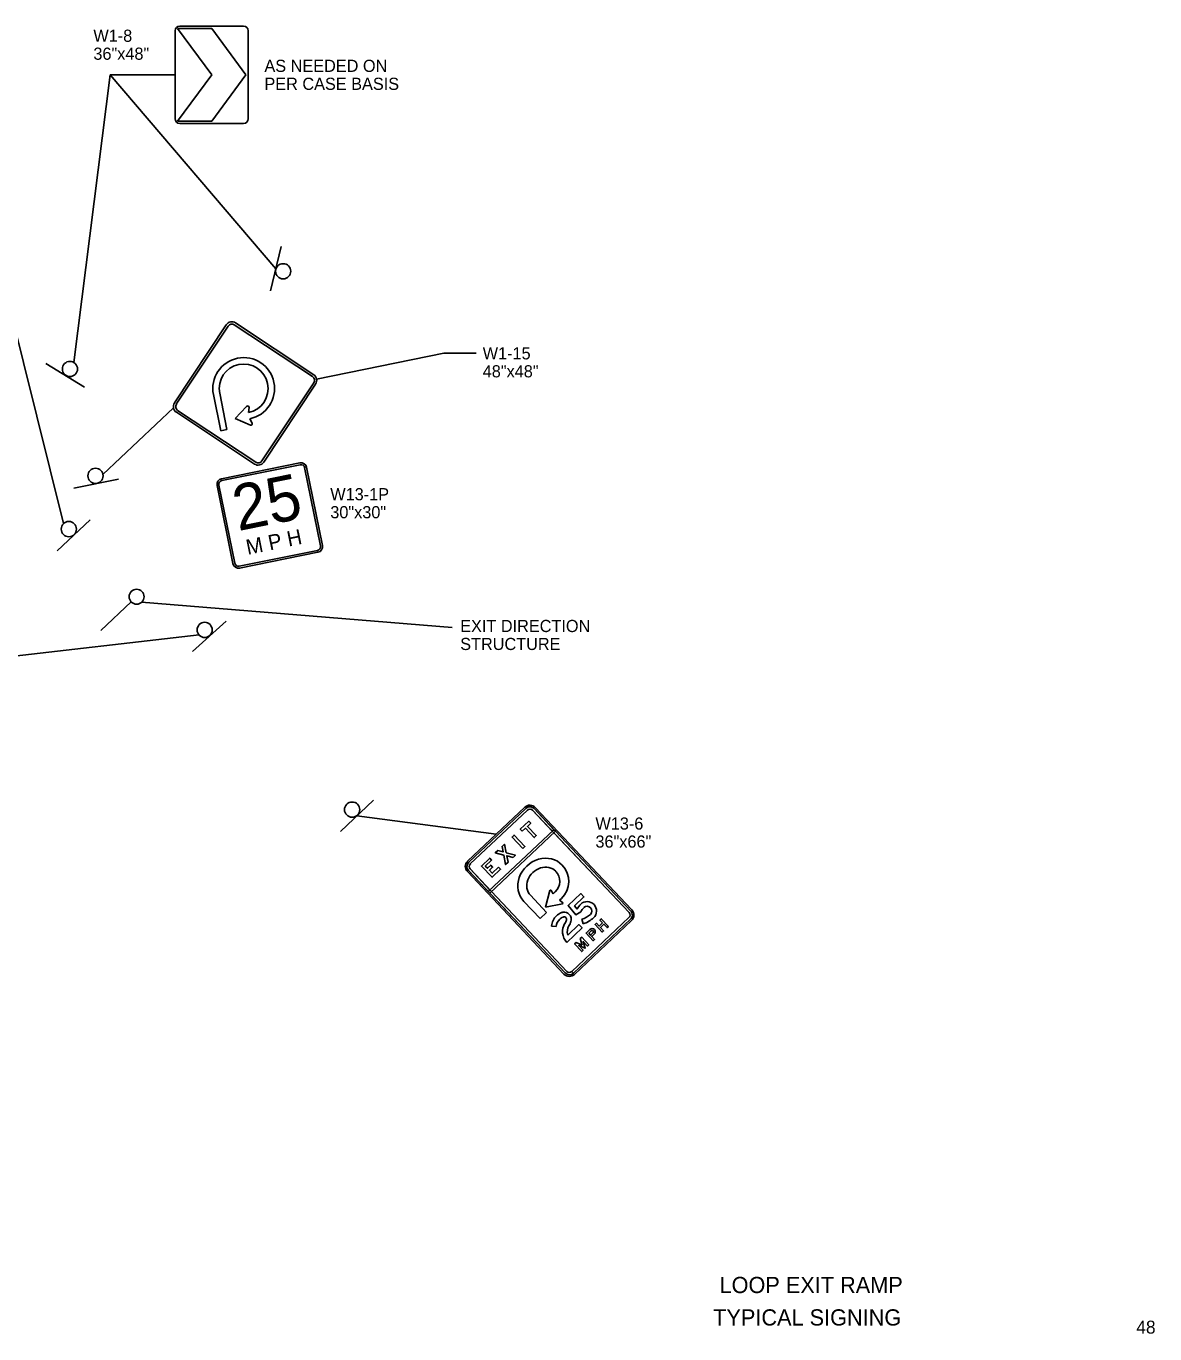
# Model space of a CAD drawing. Extents: x 571683 to 574814, y 1530838 to 1532905.
# Drawn here: x 573075 to 574814, y 1530889 to 1532905 of the extents above; entities that cross this region are included whole.
import ezdxf

# ---------------------------------------------------------------- set-up
doc = ezdxf.new("R2010")
doc.units = 0
for name, color, linetype in [('SignDetail', 7, 'Continuous'), ('SignPanel', 7, 'Continuous'), ('TextLabel', 7, 'Continuous'), ('TextMisc', 7, 'Continuous'), ('TextShtNo', 7, 'Continuous')]:
    doc.layers.add(name, color=color, linetype=linetype)

msp = doc.modelspace()

# ---------------------------------------------------------------- linework, layer by layer
at = {"layer": 'SignDetail'}
for p, q in [((573148.6, 1532386.1), (573204.7, 1532829.3)), ((573204.7, 1532829.3), (573304.7, 1532829.5)), ((573459.6, 1532530.7), (573204.7, 1532829.3)), ((573132.8, 1532137.8), (572992.3, 1532700.8)), ((573467.8, 1532564.8), (573451.5, 1532496.7)), ((573522.6, 1532360.6), (573718.6, 1532400.3)), ((573718.6, 1532400.3), (573768.6, 1532400.3)), ((573105.3, 1532384.6), (573165.1, 1532348.3)), ((573193.3, 1532213.7), (573302, 1532316)), ((573148.7, 1532192.4), (573217.3, 1532206.3)), ((573122.7, 1532095.6), (573173.7, 1532143.6)), ((573236.8, 1532017.1), (573190.1, 1531973.2)), ((573253, 1532016.6), (573731.4, 1531977.7)), ((573331.2, 1531940.7), (573383.2, 1531987.6)), ((572955.7, 1531921.8), (573341.4, 1531966.1)), ((573559.2, 1531663.3), (573610.1, 1531711.3)), ((573584.7, 1531687.3), (573799.4, 1531659.1))]:
    msp.add_line(p, q, dxfattribs=at)
for centre, radius in [((573471.1, 1532526.7), 11.7), ((573142.5, 1532376.1), 11.7), ((573181.9, 1532211.4), 11.7), ((573140.8, 1532129.3), 11.7), ((573140.8, 1532129.3), 11.7), ((573245.2, 1532025), 11.5), ((573245.2, 1532025), 11.5), ((573350.1, 1531973.9), 11.7), ((573577.3, 1531696.9), 11.7)]:
    msp.add_circle(centre, radius, dxfattribs=at)
at = {"layer": 'SignPanel'}
for p, q in [((573311.7, 1532904.5), (573410.1, 1532904.5)), ((573304.7, 1532897.5), (573304.7, 1532897.5)), ((573360.9, 1532829.5), (573308.2, 1532901)), ((573308.2, 1532901), (573360.9, 1532901)), ((573360.9, 1532901), (573413.7, 1532829.5)), ((573308.2, 1532758), (573360.9, 1532829.5)), ((573413.7, 1532829.5), (573360.9, 1532758)), ((573360.9, 1532758), (573308.2, 1532758)), ((573383.4, 1532444.2), (573303.6, 1532323.7)), ((573386.3, 1532442.3), (573306.4, 1532321.8)), ((573516.3, 1532364.3), (573395.8, 1532444.2)), ((573518.2, 1532367.2), (573397.7, 1532447.1)), ((573384.5, 1532282.8), (573373.3, 1532338.6)), ((573438.3, 1532234.4), (573518.2, 1532354.8)), ((573441.2, 1532232.5), (573521.1, 1532352.9)), ((573363.5, 1532336.6), (573374.8, 1532280.8)), ((573414.8, 1532318.5), (573397, 1532299.9)), ((573306.5, 1532309.4), (573426.9, 1532229.6)), ((573308.4, 1532312.3), (573428.8, 1532232.4)), ((573397, 1532299.9), (573420.6, 1532289.5)), ((573417.6, 1532309.1), (573418.5, 1532316.8)), ((573423.3, 1532292.6), (573419.6, 1532299.4)), ((573374.8, 1532280.8), (573384.5, 1532282.8)), ((573496.7, 1532231.4), (573376.1, 1532207)), ((573497.3, 1532228.6), (573376.7, 1532204.1)), ((573528.6, 1532103.4), (573504.2, 1532224)), ((573531.5, 1532103.9), (573507.1, 1532224.6)), ((573372.1, 1532197.2), (573396.5, 1532076.6)), ((573369.2, 1532196.7), (573393.6, 1532076.1)), ((573403.4, 1532072.1), (573524, 1532096.5)), ((573404, 1532069.2), (573524.6, 1532093.6)), ((573843.4, 1531700.6), (573755.4, 1531617.5)), ((573845.1, 1531698.7), (573757.1, 1531615.7)), ((573845.1, 1531698.7), (573757.1, 1531615.7)), ((573847.5, 1531696.2), (573759.5, 1531613.2)), ((573759.5, 1531613.2), (573847.5, 1531696.2)), ((573759.5, 1531613.2), (573847.5, 1531696.2)), ((574004.2, 1531538.1), (573855.3, 1531696)), ((573855.3, 1531696), (574004.2, 1531538.1)), ((573855.3, 1531696), (573885.8, 1531663.6)), ((574006.7, 1531540.5), (573857.8, 1531698.4)), ((573888.4, 1531666), (573857.8, 1531698.4)), ((574008.5, 1531542.2), (573859.6, 1531700.1)), ((573888.4, 1531666), (573787.2, 1531570.6)), ((573888.4, 1531666), (573787.2, 1531570.6)), ((573888.4, 1531666), (573787.2, 1531570.6)), ((573789.6, 1531568.1), (573890.8, 1531663.5)), ((573789.6, 1531568.1), (573890.8, 1531663.5)), ((573789.6, 1531568.1), (573890.8, 1531663.5)), ((573885.8, 1531663.6), (573888.4, 1531666)), ((573890.8, 1531663.5), (573888.2, 1531661.1)), ((573888.2, 1531661.1), (574004.2, 1531538.1)), ((573890.8, 1531663.5), (573888.4, 1531666)), ((573890.8, 1531663.5), (573888.4, 1531666)), ((573890.8, 1531663.5), (573888.4, 1531666)), ((574006.7, 1531540.5), (573890.8, 1531663.5)), ((573754.9, 1531601.3), (573903.8, 1531443.4)), ((573756.7, 1531603), (573905.6, 1531445.1)), ((573756.7, 1531603), (573787.2, 1531570.6)), ((573759.3, 1531605.4), (573908.2, 1531447.6)), ((573908.2, 1531447.6), (573759.3, 1531605.4)), ((573789.8, 1531573), (573759.3, 1531605.4)), ((573787.2, 1531570.6), (573789.8, 1531573)), ((573884.2, 1531572.4), (573887.2, 1531567.3)), ((573787.2, 1531570.6), (573789.6, 1531568.1)), ((573787.2, 1531570.6), (573789.6, 1531568.1)), ((573787.2, 1531570.6), (573789.6, 1531568.1)), ((573792.2, 1531570.5), (573789.6, 1531568.1)), ((573789.6, 1531568.1), (573905.6, 1531445.1)), ((573908.2, 1531447.6), (573792.2, 1531570.5)), ((573866.9, 1531529.1), (573842, 1531555.4)), ((573852.1, 1531564.8), (573876.9, 1531538.5)), ((573875.4, 1531546.6), (573882, 1531572.1)), ((573887.2, 1531567.3), (573890.4, 1531570.2)), ((573899.8, 1531560.1), (573896.7, 1531557.3)), ((573896.7, 1531557.3), (573901.7, 1531553.9)), ((573876.9, 1531538.5), (573866.9, 1531529.1)), ((573901.3, 1531551.8), (573875.4, 1531546.6)), ((573915.9, 1531447.3), (574003.9, 1531530.4)), ((574003.9, 1531530.4), (573916, 1531447.3)), ((574003.9, 1531530.4), (573916, 1531447.3)), ((573918.4, 1531444.8), (574006.4, 1531527.8)), ((573918.4, 1531444.8), (574006.4, 1531527.8)), ((573920.1, 1531443), (574008.1, 1531526)), ((573933.5, 1531521), (573931.4, 1531527.8)), ((573933.5, 1531521), (573931.4, 1531527.8)), ((573933.5, 1531521), (573931.4, 1531527.8)), ((573942, 1531506.5), (573945.8, 1531510)), ((573942, 1531506.5), (573945.8, 1531510)), ((573942, 1531506.5), (573945.8, 1531510)), ((573946.7, 1531501.5), (573950.5, 1531505)), ((573918.3, 1531444.8), (573915.9, 1531447.3)), ((573918.3, 1531444.8), (573915.9, 1531447.3)), ((573916, 1531447.3), (573918.4, 1531444.8)), ((573916, 1531447.3), (573918.4, 1531444.8))]:
    msp.add_line(p, q, dxfattribs=at)
for points in [[(573304.7, 1532761.6), (573304.7, 1532897.5)], [(573417.2, 1532897.5), (573417.2, 1532761.6)], [(573410.1, 1532754.5), (573311.7, 1532754.5)], [(573929.9, 1531539.4), (573922.2, 1531534.6), (573910.2, 1531549.1), (573929.7, 1531567.5), (573934.6, 1531562.3), (573920.1, 1531548.5), (573924, 1531543.7)], [(573929.9, 1531539.4), (573922.2, 1531534.6), (573910.2, 1531549.1), (573929.7, 1531567.5), (573934.6, 1531562.3), (573920.1, 1531548.5), (573924, 1531543.7)], [(573929.9, 1531539.4), (573922.2, 1531534.6), (573910.2, 1531549.1), (573929.7, 1531567.5), (573934.6, 1531562.3), (573920.1, 1531548.5), (573924, 1531543.7)], [(573891.7, 1531516.7), (573884.5, 1531517.5)], [(573891.7, 1531516.7), (573884.5, 1531517.5)], [(573891.7, 1531516.7), (573884.5, 1531517.5)], [(573909.7, 1531503.6), (573926.9, 1531519.8), (573931.8, 1531514.6), (573908.3, 1531492.3)], [(573909.7, 1531503.6), (573926.9, 1531519.8), (573931.8, 1531514.6), (573908.3, 1531492.3)], [(573909.7, 1531503.6), (573926.9, 1531519.8), (573931.8, 1531514.6), (573908.3, 1531492.3)], [(573943.8, 1531512.1), (573938, 1531506.6), (573948.9, 1531494.9), (573951, 1531496.9), (573946.7, 1531501.5)], [(573943.8, 1531512.1), (573938, 1531506.6), (573948.9, 1531494.9), (573951, 1531496.9), (573942, 1531506.5)], [(573943.8, 1531512.1), (573938, 1531506.6), (573948.9, 1531494.9), (573951, 1531496.9), (573942, 1531506.5)], [(573948.5, 1531507.1), (573944.8, 1531503.6), (573942, 1531506.5)], [(573948.5, 1531507.1), (573944.8, 1531503.6), (573946.7, 1531501.5), (573950.5, 1531505)], [(573948.5, 1531507.1), (573944.8, 1531503.6), (573946.7, 1531501.5), (573950.5, 1531505)]]:
    msp.add_lwpolyline(points, dxfattribs=at)
for points in [[(573839.5, 1531663.5), (573844.5, 1531668.2), (573858, 1531653.9), (573861.1, 1531656.8), (573847.6, 1531671.1), (573852.6, 1531675.8), (573849.6, 1531679), (573836.5, 1531666.6)], [(573839.5, 1531663.5), (573844.5, 1531668.2), (573858, 1531653.9), (573861.1, 1531656.8), (573847.6, 1531671.1), (573852.6, 1531675.8), (573849.6, 1531679), (573836.5, 1531666.6)], [(573839.5, 1531663.5), (573844.5, 1531668.2), (573858, 1531653.9), (573861.1, 1531656.8), (573847.6, 1531671.1), (573852.6, 1531675.8), (573849.6, 1531679), (573836.5, 1531666.6)], [(573840.3, 1531637.2), (573823.9, 1531654.7), (573827, 1531657.6), (573843.5, 1531640.2)], [(573840.3, 1531637.2), (573823.9, 1531654.7), (573827, 1531657.6), (573843.5, 1531640.2)], [(573840.3, 1531637.2), (573823.9, 1531654.7), (573827, 1531657.6), (573843.5, 1531640.2)], [(573825.4, 1531623.1), (573815.7, 1531625.7), (573817.7, 1531615.8), (573813.9, 1531612.3), (573811.1, 1531626.9), (573798, 1531630.3), (573801.7, 1531633.8), (573810.1, 1531631.6), (573808.4, 1531640.1), (573812.1, 1531643.6), (573814.8, 1531630.4), (573829.1, 1531626.6)], [(573825.4, 1531623.1), (573815.7, 1531625.7), (573817.7, 1531615.8), (573813.9, 1531612.3), (573811.1, 1531626.9), (573798, 1531630.3), (573801.7, 1531633.8), (573810.1, 1531631.6), (573808.4, 1531640.1), (573812.1, 1531643.6), (573814.8, 1531630.4), (573829.1, 1531626.6)], [(573825.4, 1531623.1), (573815.7, 1531625.7), (573817.7, 1531615.8), (573813.9, 1531612.3), (573811.1, 1531626.9), (573798, 1531630.3), (573801.7, 1531633.8), (573810.1, 1531631.6), (573808.4, 1531640.1), (573812.1, 1531643.6), (573814.8, 1531630.4), (573829.1, 1531626.6)], [(573803.1, 1531608.1), (573793.2, 1531598.7), (573788.8, 1531603.4), (573793.9, 1531608.2), (573790.9, 1531611.4), (573785.8, 1531606.5), (573782.6, 1531609.8), (573792.3, 1531619), (573789.4, 1531622.1), (573776.5, 1531610), (573793, 1531592.6), (573806.1, 1531604.9)], [(573803.1, 1531608.1), (573793.2, 1531598.7), (573788.8, 1531603.4), (573793.9, 1531608.2), (573790.9, 1531611.4), (573785.8, 1531606.5), (573782.6, 1531609.8), (573792.3, 1531619), (573789.4, 1531622.1), (573776.5, 1531610), (573793, 1531592.6), (573806.1, 1531604.9)], [(573803.1, 1531608.1), (573793.2, 1531598.7), (573788.8, 1531603.4), (573793.9, 1531608.2), (573790.9, 1531611.4), (573785.8, 1531606.5), (573782.6, 1531609.8), (573792.3, 1531619), (573789.4, 1531622.1), (573776.5, 1531610), (573793, 1531592.6), (573806.1, 1531604.9)], [(573963.4, 1531522.2), (573958.1, 1531517.3), (573953.9, 1531521.7), (573951.8, 1531519.7), (573962.8, 1531508.1), (573964.9, 1531510), (573960.1, 1531515.2), (573965.3, 1531520.1), (573970.2, 1531515), (573972.3, 1531517), (573961.3, 1531528.6), (573959.2, 1531526.6)], [(573963.4, 1531522.2), (573958.1, 1531517.3), (573953.9, 1531521.7), (573951.8, 1531519.7), (573962.8, 1531508.1), (573964.9, 1531510), (573960.1, 1531515.2), (573965.3, 1531520.1), (573970.2, 1531515), (573972.3, 1531517), (573961.3, 1531528.6), (573959.2, 1531526.6)], [(573963.4, 1531522.2), (573958.1, 1531517.3), (573953.9, 1531521.7), (573951.8, 1531519.7), (573962.8, 1531508.1), (573964.9, 1531510), (573960.1, 1531515.2), (573965.3, 1531520.1), (573970.2, 1531515), (573972.3, 1531517), (573961.3, 1531528.6), (573959.2, 1531526.6)], [(573932, 1531488.2), (573928.9, 1531498), (573931.1, 1531500.1), (573942.1, 1531488.5), (573940, 1531486.5), (573933.3, 1531493.6), (573936.6, 1531483.3), (573926.6, 1531487.3), (573933.2, 1531480.2), (573931.2, 1531478.2), (573920.2, 1531489.8), (573922.4, 1531491.9)], [(573932, 1531488.2), (573928.9, 1531498), (573931.1, 1531500.1), (573942.1, 1531488.5), (573940, 1531486.5), (573933.3, 1531493.6), (573936.6, 1531483.3), (573926.6, 1531487.3), (573933.2, 1531480.2), (573931.2, 1531478.2), (573920.2, 1531489.8), (573922.4, 1531491.9)], [(573932, 1531488.2), (573928.9, 1531498), (573931.1, 1531500.1), (573942.1, 1531488.5), (573940, 1531486.5), (573933.3, 1531493.6), (573936.6, 1531483.3), (573926.6, 1531487.3), (573933.2, 1531480.2), (573931.2, 1531478.2), (573920.2, 1531489.8), (573922.4, 1531491.9)]]:
    msp.add_lwpolyline(points, close=True, dxfattribs=at)
for centre, radius, start, end in [((573311.7, 1532897.5), 7.03, 90, 180), ((573410.1, 1532897.5), 7.03, 0, 90), ((573311.7, 1532761.6), 7.03, 180, 270), ((573410.1, 1532761.6), 7.03, 270, 0), ((573392, 1532438.5), 10.3, 56.44, 146.44), ((573392, 1532438.5), 6.88, 56.44, 146.44), ((573410.2, 1532346), 47.6, 281.44, 191.44), ((573410.2, 1532346), 37.7, 281.44, 191.44), ((573512.5, 1532358.6), 6.88, 326.44, 56.44), ((573512.5, 1532358.6), 10.3, 326.44, 56.44), ((573312.2, 1532318), 10.3, 146.44, 236.44), ((573312.2, 1532318), 6.88, 146.44, 236.44), ((573416.3, 1532317), 2.17, 353.7302, 136.431), ((573421.4, 1532291.5), 2.17, 246.2833, 28.984), ((573432.6, 1532238.2), 10.3, 236.44, 326.44), ((573432.6, 1532238.2), 6.88, 236.44, 326.44), ((573498.5, 1532222.8), 8.79, 11.44, 101.44), ((573498.5, 1532222.8), 5.86, 11.44, 101.44), ((573377.8, 1532198.4), 8.79, 101.44, 191.44), ((573377.8, 1532198.4), 5.86, 101.44, 191.44), ((573522.9, 1532102.2), 5.86, 281.44, 11.44), ((573522.9, 1532102.2), 8.79, 281.44, 11.44), ((573402.3, 1532077.8), 5.86, 191.44, 281.44), ((573402.3, 1532077.8), 8.79, 191.44, 281.44), ((573851.3, 1531692.2), 11.5, 43.3307, 133.3307), ((573851.3, 1531692.2), 9, 43.3307, 133.3307), ((573851.3, 1531692.2), 9, 43.3307, 133.3307), ((573851.3, 1531692.2), 5.5, 43.3307, 133.3307), ((573851.3, 1531692.2), 5.5, 43.3307, 133.3307), ((573851.3, 1531692.2), 5.5, 43.3307, 133.3307), ((573763.3, 1531609.2), 11.5, 133.3307, 223.3307), ((573763.3, 1531609.2), 9, 133.3307, 223.3307), ((573763.3, 1531609.2), 9, 133.3307, 223.3307), ((573763.3, 1531609.2), 5.5, 133.3307, 223.3307), ((573763.3, 1531609.2), 5.5, 133.3307, 223.3307), ((573763.3, 1531609.2), 5.5, 133.3307, 223.3307), ((573874.9, 1531586.4), 22.4, 313.6525, 43.3307), ((573874.9, 1531586.4), 36.2, 313.3834, 43.3307), ((574000.2, 1531534.4), 5.5, 313.3307, 43.3307), ((574000.2, 1531534.4), 5.5, 313.3307, 43.3307), ((574000.2, 1531534.4), 5.5, 313.3307, 43.3307), ((574000.2, 1531534.4), 9, 313.3307, 43.3307), ((574000.2, 1531534.4), 9, 313.3307, 43.3307), ((574000.2, 1531534.4), 11.5, 313.3307, 43.3307), ((573912.2, 1531451.3), 11.5, 223.3307, 313.3307), ((573912.2, 1531451.3), 9, 223.3307, 313.3307), ((573912.2, 1531451.3), 9, 223.3307, 313.3307), ((573912.2, 1531451.3), 5.5, 223.3307, 313.3307), ((573912.2, 1531451.3), 5.5, 223.3307, 313.3307), ((573912.2, 1531451.3), 5.5, 223.3307, 313.3307)]:
    msp.add_arc(centre, radius, start, end, dxfattribs=at)
for centre, major_axis, ratio, start_param, end_param in [((573871.6, 1531583.3), (29.6, 27.9), 0.90173, 0, 3.141593), ((573871.6, 1531583.3), (19.6, 18.5), 0.851426, 0, 3.141593), ((573883.2, 1531571.8), (0.87, 0.82), 0.999992, 6.05179, 8.413502), ((573901, 1531552.9), (0.87, 0.82), 0.999992, 4.152868, 6.5073), ((573939.6, 1531540.7), (-9.9, 10.5), 0.999998, 3.141593, 6.283185), ((573939.6, 1531540.7), (-9.9, 10.5), 0.999998, 3.141593, 6.283185), ((573939.6, 1531540.7), (-9.9, 10.5), 0.999998, 3.141593, 6.283185), ((573910.2, 1531514.6), (-17.7, 18.8), 0.999998, 0, 0.70376), ((573910.2, 1531514.6), (-17.7, 18.8), 0.999998, 0, 0.70376), ((573910.2, 1531514.6), (-17.7, 18.8), 0.999998, 0, 0.70376), ((573909.8, 1531515), (-17.4, 18.4), 0.999998, 6.02311, 6.283185), ((573909.8, 1531515), (-17.4, 18.4), 0.999998, 6.02311, 6.283185), ((573909.8, 1531515), (-17.4, 18.4), 0.999998, 6.02311, 6.283185), ((573904.8, 1531524.3), (-10.1, 10.7), 0.999998, 5.706931, 6.02311), ((573904.8, 1531524.3), (-10.1, 10.7), 0.999998, 5.706931, 6.02311), ((573904.8, 1531524.3), (-10.1, 10.7), 0.999998, 5.706931, 6.02311), ((573904.1, 1531528), (-7.5, 7.95), 0.999998, 4.712389, 5.706931), ((573904.1, 1531528), (-7.5, 7.95), 0.999998, 4.712389, 5.706931), ((573904.1, 1531528), (-7.5, 7.95), 0.999998, 4.712389, 5.706931), ((573903.9, 1531527.8), (-7.67, 8.13), 0.999998, 3.626327, 4.712389), ((573903.9, 1531527.8), (-7.67, 8.13), 0.999998, 3.626327, 4.712389), ((573903.9, 1531527.8), (-7.67, 8.13), 0.999998, 3.626327, 4.712389), ((573949.5, 1531530.2), (-19.8, 20.9), 0.999998, 0, 0.326688), ((573949.5, 1531530.2), (-19.8, 20.9), 0.999998, 0, 0.326688), ((573949.5, 1531530.2), (-19.8, 20.9), 0.999998, 0, 0.326688), ((573949.5, 1531530.2), (-14.8, 15.7), 0.999998, 0, 0.374869), ((573949.5, 1531530.2), (-14.8, 15.7), 0.999998, 0, 0.374869), ((573949.5, 1531530.2), (-14.8, 15.7), 0.999998, 0, 0.374869), ((573921.6, 1531559.8), (-22.9, 24.3), 0.999998, 2.68226, 3.141593), ((573921.6, 1531559.8), (-22.9, 24.3), 0.999998, 2.68226, 3.141593), ((573921.6, 1531559.8), (-22.9, 24.3), 0.999998, 2.68226, 3.141593), ((573939.6, 1531540.7), (-4.94, 5.24), 0.999998, 3.141593, 6.283185), ((573939.6, 1531540.7), (-4.94, 5.24), 0.999998, 3.141593, 6.283185), ((573939.6, 1531540.7), (-4.94, 5.24), 0.999998, 3.141593, 6.283185), ((573910.2, 1531514.6), (-12.8, 13.5), 0.999998, 0, 0.70376), ((573910.2, 1531514.6), (-12.8, 13.5), 0.999998, 0, 0.70376), ((573910.2, 1531514.6), (-12.8, 13.5), 0.999998, 0, 0.70376), ((573909.8, 1531515), (-12.4, 13.2), 0.999998, 6.02311, 6.283185), ((573909.8, 1531515), (-12.4, 13.2), 0.999998, 6.02311, 6.283185), ((573909.8, 1531515), (-12.4, 13.2), 0.999998, 6.02311, 6.283185), ((573925.8, 1531508.9), (-16.6, 17.6), 0.999998, 0.25053, 1.570796), ((573925.8, 1531508.9), (-16.6, 17.6), 0.999998, 0.25053, 1.570796), ((573925.8, 1531508.9), (-16.6, 17.6), 0.999998, 0.25053, 1.570796), ((573904.8, 1531524.3), (-5.13, 5.43), 0.999998, 5.706931, 6.02311), ((573904.8, 1531524.3), (-5.13, 5.43), 0.999998, 5.706931, 6.02311), ((573904.8, 1531524.3), (-5.13, 5.43), 0.999998, 5.706931, 6.02311), ((573904.1, 1531528), (-2.56, 2.72), 0.999998, 4.712389, 5.706931), ((573904.1, 1531528), (-2.56, 2.72), 0.999998, 4.712389, 5.706931), ((573904.1, 1531528), (-2.56, 2.72), 0.999998, 4.712389, 5.706931), ((573886.4, 1531533.9), (-15.5, 16.4), 0.999998, 3.392123, 3.626327), ((573886.4, 1531533.9), (-15.5, 16.4), 0.999998, 3.392123, 3.626327), ((573886.4, 1531533.9), (-15.5, 16.4), 0.999998, 3.392123, 3.626327), ((573903.9, 1531527.8), (-2.73, 2.89), 0.999998, 3.626327, 4.712389), ((573903.9, 1531527.8), (-2.73, 2.89), 0.999998, 3.626327, 4.712389), ((573903.9, 1531527.8), (-2.73, 2.89), 0.999998, 3.626327, 4.712389), ((573925.8, 1531508.9), (-11.6, 12.3), 0.999998, 0.25053, 1.132058), ((573925.8, 1531508.9), (-11.6, 12.3), 0.999998, 0.25053, 1.132058), ((573925.8, 1531508.9), (-11.6, 12.3), 0.999998, 0.25053, 1.132058), ((573886.4, 1531533.9), (-20.4, 21.6), 0.999998, 3.392123, 3.626327), ((573886.4, 1531533.9), (-20.4, 21.6), 0.999998, 3.392123, 3.626327), ((573886.4, 1531533.9), (-20.4, 21.6), 0.999998, 3.392123, 3.626327), ((573921.6, 1531559.8), (-27.9, 29.5), 0.999998, 2.68226, 3.141593), ((573921.6, 1531559.8), (-27.9, 29.5), 0.999998, 2.68226, 3.141593), ((573921.6, 1531559.8), (-27.9, 29.5), 0.999998, 2.68226, 3.141593), ((573947.2, 1531508.6), (-3.35, 3.55), 0.999998, 3.141593, 6.283185), ((573947.2, 1531508.6), (-3.35, 3.55), 0.999998, 3.141593, 6.283185), ((573947.2, 1531508.6), (-3.35, 3.55), 0.999998, 3.141593, 6.283185), ((573947.2, 1531508.6), (-1.37, 1.45), 0.999998, 3.141593, 6.283185), ((573947.2, 1531508.6), (-1.37, 1.45), 0.999998, 3.141593, 6.283185), ((573947.2, 1531508.6), (-1.37, 1.45), 0.999998, 3.141593, 6.283185)]:
    msp.add_ellipse(centre, major_axis=major_axis, ratio=ratio, start_param=start_param, end_param=end_param, dxfattribs=at)

# ---------------------------------------------------------------- texts
for s, height, p in [('25', 70.31, (573401.5, 1532126.1)), ('M P H', 23.41, (573416.4, 1532089.5))]:
    msp.add_text(s, height=height, rotation=11.44, dxfattribs=at).set_placement(p)
at = {"layer": 'TextLabel'}
for s, p in [('W1-8', (573178.6, 1532880.4)), ('36"x48"', (573178.6, 1532852.7)), ('AS NEEDED ON', (573442.2, 1532834)), ('PER CASE BASIS', (573442.2, 1532806.3)), ('W1-15', (573778.6, 1532390.9)), ('48"x48"', (573778.6, 1532363.2)), ('W13-1P', (573543.7, 1532173.7)), ('30"x30"', (573543.7, 1532146)), ('EXIT DIRECTION', (573743.9, 1531970.6)), ('STRUCTURE', (573743.9, 1531942.9)), ('W13-6', (573952.3, 1531666.1)), ('36"x66"', (573952.3, 1531638.3))]:
    msp.add_text(s, height=18.74, dxfattribs=at).set_placement(p)
at = {"layer": 'TextMisc'}
for s, p in [('     LOOP EXIT RAMP     ', (574097.1, 1530951.7)), ('    TYPICAL SIGNING     ', (574096.6, 1530901.7))]:
    msp.add_text(s, height=25, rotation=360, dxfattribs=at).set_placement(p)
at = {"layer": 'TextShtNo'}
msp.add_text('48', height=20, rotation=360, dxfattribs=at).set_placement((574785.8, 1530889.2))

doc.saveas('drawing.dxf')
